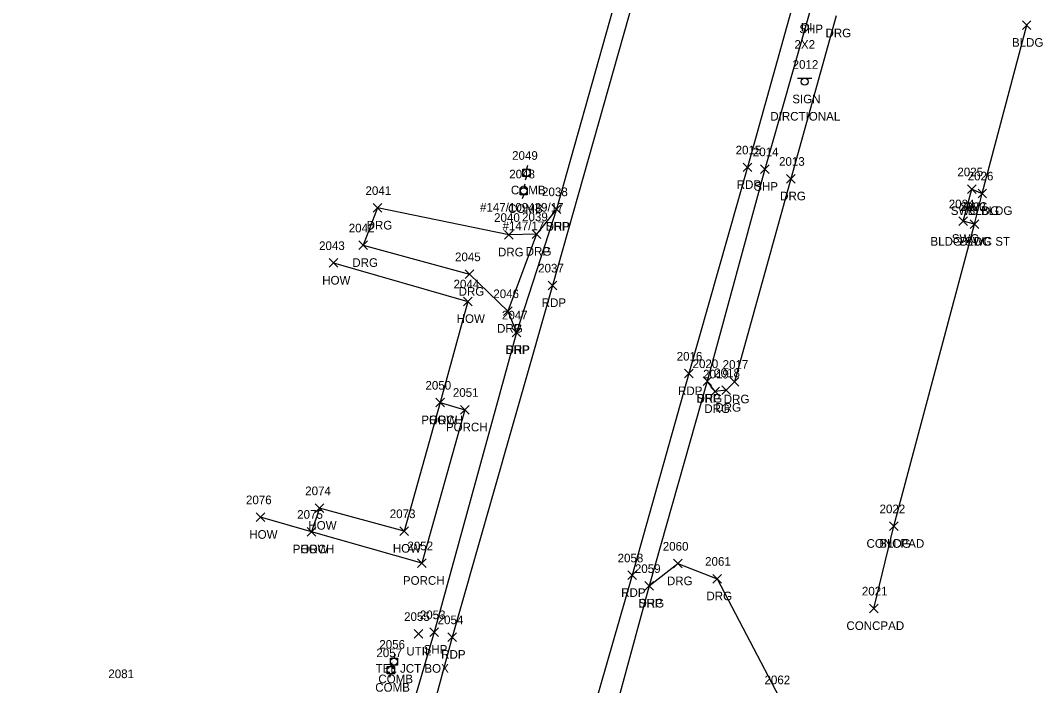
# Model space of a CAD drawing. Extents: x 1443071 to 1445292, y 614024 to 622563.
# Drawn here: x 1444555.8 to 1444792.5, y 622316.6 to 622470.6 of the extents above; entities that cross this region are included whole.
import ezdxf

# ---------------------------------------------------------------- set-up
doc = ezdxf.new("R2010")
doc.units = 0
for name, color, linetype in [('D_A', 7, 'Continuous'), ('D_C', 7, 'Continuous'), ('L_A', 7, 'Continuous'), ('L_I', 7, 'Continuous'), ('L_TIC', 7, 'Continuous'), ('LBC', 7, 'Continuous'), ('LBF', 7, 'Continuous'), ('LS', 7, 'Continuous'), ('P_A', 7, 'Continuous'), ('P_I', 7, 'Continuous'), ('P_TIC', 7, 'Continuous'), ('PET', 7, 'Continuous'), ('PSP', 7, 'Continuous'), ('R_A', 7, 'Continuous'), ('R_I', 7, 'Continuous'), ('R_TIC', 7, 'Continuous'), ('RDG', 7, 'Continuous'), ('RDP', 7, 'Continuous'), ('RSW', 7, 'Continuous'), ('S_A', 7, 'Continuous'), ('S_C', 7, 'Continuous'), ('S_I', 7, 'Continuous'), ('SSGN', 7, 'Continuous'), ('U_A', 7, 'Continuous'), ('U_C', 7, 'Continuous'), ('U_I', 7, 'Continuous'), ('UDEFAULT', 7, 'Continuous'), ('UP', 7, 'Continuous')]:
    doc.layers.add(name, color=color, linetype=linetype)

msp = doc.modelspace()

# ---------------------------------------------------------------- linework, layer by layer
at = {"layer": 'L_TIC'}
for points in [[(1444787.84, 622468.55), (1444789.84, 622470.55)], [(1444789.84, 622468.55), (1444787.84, 622470.55)], [(1444777.57, 622429.6), (1444779.57, 622431.6)], [(1444779.57, 622429.6), (1444777.57, 622431.6)], [(1444775.74, 622422.48), (1444777.74, 622424.48)], [(1444777.74, 622422.48), (1444775.74, 622424.48)], [(1444627.32, 622413.48), (1444629.32, 622415.48)], [(1444629.32, 622413.48), (1444627.32, 622415.48)], [(1444658.46, 622404.59), (1444660.46, 622406.59)], [(1444660.46, 622404.59), (1444658.46, 622406.59)], [(1444652.04, 622381.14), (1444654.04, 622383.14)], [(1444654.04, 622381.14), (1444652.04, 622383.14)], [(1444652.04, 622381.14), (1444654.04, 622383.14)], [(1444654.04, 622381.14), (1444652.04, 622383.14)], [(1444657.73, 622379.48), (1444659.73, 622381.48)], [(1444659.73, 622379.48), (1444657.73, 622381.48)], [(1444624.11, 622356.7), (1444626.11, 622358.7)], [(1444626.11, 622356.7), (1444624.11, 622358.7)], [(1444610.44, 622354.61), (1444612.44, 622356.61)], [(1444612.44, 622354.61), (1444610.44, 622356.61)], [(1444757.11, 622352.52), (1444759.11, 622354.52)], [(1444759.11, 622352.52), (1444757.11, 622354.52)], [(1444757.11, 622352.52), (1444759.11, 622354.52)], [(1444759.11, 622352.52), (1444757.11, 622354.52)], [(1444622.25, 622351.24), (1444624.25, 622353.24)], [(1444624.25, 622351.24), (1444622.25, 622353.24)], [(1444622.25, 622351.24), (1444624.25, 622353.24)], [(1444624.25, 622351.24), (1444622.25, 622353.24)], [(1444643.69, 622351.39), (1444645.69, 622353.39)], [(1444645.69, 622351.39), (1444643.69, 622353.39)], [(1444647.77, 622343.95), (1444649.77, 622345.95)], [(1444649.77, 622343.95), (1444647.77, 622345.95)], [(1444752.45, 622333.48), (1444754.45, 622335.48)], [(1444754.45, 622333.48), (1444752.45, 622335.48)], [(1444752.45, 622333.48), (1444754.45, 622335.48)], [(1444754.45, 622333.48), (1444752.45, 622335.48)]]:
    msp.add_lwpolyline(points, dxfattribs=at)
at = {"layer": 'LBC'}
for points in [[(1444758.11, 622353.52), (1444776.74, 622423.48), (1444778.57, 622430.6), (1444788.84, 622469.55)], [(1444628.32, 622414.48), (1444659.46, 622405.59), (1444653.04, 622382.14), (1444644.69, 622352.39), (1444625.11, 622357.7), (1444623.25, 622352.24), (1444611.44, 622355.61)]]:
    msp.add_lwpolyline(points, dxfattribs=at)
at = {"layer": 'LBF'}
msp.add_lwpolyline([(1444653.04, 622382.14), (1444658.73, 622380.48), (1444648.77, 622344.95), (1444623.25, 622352.24)], dxfattribs=at)
at = {"layer": 'LS'}
msp.add_lwpolyline([(1444753.45, 622334.48), (1444758.11, 622353.52)], dxfattribs=at)
at = {"layer": 'P_TIC'}
for points in [[(1444723.21, 622435.63), (1444725.21, 622437.63)], [(1444725.21, 622435.63), (1444723.21, 622437.63)], [(1444727.21, 622435.2), (1444729.21, 622437.2)], [(1444729.21, 622435.2), (1444727.21, 622437.2)], [(1444678.96, 622425.95), (1444680.96, 622427.95)], [(1444680.96, 622425.95), (1444678.96, 622427.95)], [(1444678.05, 622408.28), (1444680.05, 622410.28)], [(1444680.05, 622408.28), (1444678.05, 622410.28)], [(1444669.67, 622397.4), (1444671.67, 622399.4)], [(1444671.67, 622397.4), (1444669.67, 622399.4)], [(1444709.62, 622387.87), (1444711.62, 622389.87)], [(1444711.62, 622387.87), (1444709.62, 622389.87)], [(1444713.89, 622386.13), (1444715.89, 622388.13)], [(1444715.89, 622386.13), (1444713.89, 622388.13)], [(1444696.45, 622341.15), (1444698.45, 622343.15)], [(1444698.45, 622341.15), (1444696.45, 622343.15)], [(1444700.45, 622338.69), (1444702.45, 622340.69)], [(1444702.45, 622338.69), (1444700.45, 622340.69)], [(1444650.65, 622327.99), (1444652.65, 622329.99)], [(1444652.65, 622327.99), (1444650.65, 622329.99)], [(1444654.77, 622326.83), (1444656.77, 622328.83)], [(1444656.77, 622326.83), (1444654.77, 622328.83)]]:
    msp.add_lwpolyline(points, dxfattribs=at)
at = {"layer": 'PET'}
for points in [[(1444754.44, 622544.13), (1444741.07, 622497.37), (1444724.21, 622436.63), (1444710.62, 622388.87), (1444697.45, 622342.15), (1444675, 622264.13), (1444650.85, 622183.92), (1444630.28, 622116), (1444610.88, 622049.25), (1444594.96, 621996.24), (1444563.37, 621884.27), (1444533.4, 621779.05), (1444495.09, 621640.86), (1444437.04, 621433.18), (1444409.83, 621332.84), (1444393.99, 621275.61), (1444360.23, 621155.32)], [(1444707.59, 622509.11), (1444700.19, 622484.07), (1444679.05, 622409.28), (1444655.77, 622327.83), (1444650.07, 622306.66), (1444636.13, 622255.68), (1444623.55, 622208.8), (1444606.26, 622146.53), (1444595.29, 622106.04), (1444582.56, 622060.23), (1444534.43, 621893.79), (1444481.57, 621704.27), (1444439.29, 621553.82), (1444408.11, 621445.28), (1444395.03, 621397.39), (1444367.96, 621301.44), (1444350.41, 621238.76), (1444319.14, 621126.97)]]:
    msp.add_lwpolyline(points, dxfattribs=at)
at = {"layer": 'PSP'}
for points in [[(1444703.05, 622509.58), (1444696.35, 622485.04), (1444679.96, 622426.95), (1444670.67, 622398.4), (1444651.65, 622328.99), (1444645.77, 622309.01), (1444600.31, 622147.99), (1444589.19, 622108.06), (1444575.49, 622063.15), (1444529.28, 621895.39), (1444476.53, 621706.36), (1444455.46, 621630.82), (1444442.09, 621578.45), (1444424.77, 621519.75), (1444412.09, 621475.26), (1444390.88, 621397.93), (1444363.76, 621301.82), (1444345.99, 621239.2), (1444324.65, 621163.68)], [(1444745.15, 622495.54), (1444738.65, 622472.69), (1444728.21, 622436.2), (1444714.89, 622387.13), (1444701.45, 622339.69), (1444679.77, 622260.17), (1444671.12, 622229.57), (1444657.52, 622182.26), (1444644.19, 622133.53), (1444626.95, 622072.43), (1444608.5, 622007.83), (1444599.1, 621977.5), (1444572.99, 621881.76), (1444551.74, 621805.05), (1444541.41, 621769.53), (1444519.46, 621688.51), (1444505.68, 621638.77), (1444452.32, 621450.13), (1444441.68, 621411.27), (1444418.22, 621330.76), (1444405.98, 621283.95), (1444397.04, 621252.99), (1444383.69, 621203.04)]]:
    msp.add_lwpolyline(points, dxfattribs=at)
at = {"layer": 'R_TIC'}
for points in [[(1444733.26, 622432.99), (1444735.26, 622434.99)], [(1444735.26, 622432.99), (1444733.26, 622434.99)], [(1444775.13, 622430.55), (1444777.13, 622432.55)], [(1444777.13, 622430.55), (1444775.13, 622432.55)], [(1444777.57, 622429.6), (1444779.57, 622431.6)], [(1444779.57, 622429.6), (1444777.57, 622431.6)], [(1444637.51, 622426.23), (1444639.51, 622428.23)], [(1444639.51, 622426.23), (1444637.51, 622428.23)], [(1444678.96, 622425.95), (1444680.96, 622427.95)], [(1444680.96, 622425.95), (1444678.96, 622427.95)], [(1444773.13, 622423.14), (1444775.13, 622425.14)], [(1444775.13, 622423.14), (1444773.13, 622425.14)], [(1444775.74, 622422.48), (1444777.74, 622424.48)], [(1444777.74, 622422.48), (1444775.74, 622424.48)], [(1444667.93, 622420), (1444669.93, 622422)], [(1444669.93, 622420), (1444667.93, 622422)], [(1444674.34, 622420.16), (1444676.34, 622422.16)], [(1444676.34, 622420.16), (1444674.34, 622422.16)], [(1444674.34, 622420.16), (1444676.34, 622422.16)], [(1444676.34, 622420.16), (1444674.34, 622422.16)], [(1444634.18, 622417.57), (1444636.18, 622419.57)], [(1444636.18, 622417.57), (1444634.18, 622419.57)], [(1444658.8, 622410.89), (1444660.8, 622412.89)], [(1444660.8, 622410.89), (1444658.8, 622412.89)], [(1444667.72, 622402.34), (1444669.72, 622404.34)], [(1444669.72, 622402.34), (1444667.72, 622404.34)], [(1444667.72, 622402.34), (1444669.72, 622404.34)], [(1444669.72, 622402.34), (1444667.72, 622404.34)], [(1444669.67, 622397.4), (1444671.67, 622399.4)], [(1444671.67, 622397.4), (1444669.67, 622399.4)], [(1444713.89, 622386.13), (1444715.89, 622388.13)], [(1444715.89, 622386.13), (1444713.89, 622388.13)], [(1444720.2, 622385.97), (1444722.2, 622387.97)], [(1444722.2, 622385.97), (1444720.2, 622387.97)], [(1444715.7, 622383.74), (1444717.7, 622385.74)], [(1444717.7, 622383.74), (1444715.7, 622385.74)], [(1444718.26, 622384.03), (1444720.26, 622386.03)], [(1444720.26, 622384.03), (1444718.26, 622386.03)], [(1444707.05, 622343.86), (1444709.05, 622345.86)], [(1444709.05, 622343.86), (1444707.05, 622345.86)], [(1444700.45, 622338.69), (1444702.45, 622340.69)], [(1444702.45, 622338.69), (1444700.45, 622340.69)], [(1444716.19, 622340.36), (1444718.19, 622342.36)], [(1444718.19, 622340.36), (1444716.19, 622342.36)]]:
    msp.add_lwpolyline(points, dxfattribs=at)
at = {"layer": 'RDG'}
for points in [[(1444744.76, 622471.74), (1444734.26, 622433.99), (1444721.2, 622386.97), (1444719.26, 622385.03), (1444716.7, 622384.74), (1444714.89, 622387.13)], [(1444675.34, 622421.16), (1444668.93, 622421), (1444638.51, 622427.23), (1444635.18, 622418.57), (1444659.8, 622411.89), (1444668.72, 622403.34)], [(1444701.45, 622339.69), (1444708.05, 622344.86), (1444717.19, 622341.36), (1444731.52, 622313.93), (1444723.86, 622290.24), (1444751.94, 622283.05)]]:
    msp.add_lwpolyline(points, dxfattribs=at)
at = {"layer": 'RDP'}
msp.add_lwpolyline([(1444679.96, 622426.95), (1444675.34, 622421.16), (1444668.72, 622403.34), (1444670.67, 622398.4)], dxfattribs=at)
at = {"layer": 'RSW'}
msp.add_lwpolyline([(1444776.74, 622423.48), (1444774.13, 622424.14), (1444776.13, 622431.55), (1444778.57, 622430.6)], dxfattribs=at)
at = {"layer": 'SSGN'}
for p, q in [((1444735.78, 622457.3), (1444739.11, 622457.3)), ((1444737.43, 622456.47), (1444737.43, 622456.47))]:
    msp.add_line(p, q, dxfattribs=at)
msp.add_circle((1444737.43, 622456.47), 0.833, dxfattribs=at)
at = {"layer": 'UDEFAULT'}
for points in [[(1444647.01, 622327.58), (1444649.01, 622329.58)], [(1444649.01, 622327.58), (1444647.01, 622329.58)]]:
    msp.add_lwpolyline(points, dxfattribs=at)
at = {"layer": 'UP'}
for p, q in [((1444672.19, 622434.54), (1444672.19, 622436.2)), ((1444672.19, 622436.2), (1444673.86, 622436.2)), ((1444673.27, 622437.04), (1444673.02, 622436.2)), ((1444673.02, 622435.37), (1444673.02, 622435.37)), ((1444673.86, 622436.2), (1444673.86, 622434.54)), ((1444673.86, 622434.54), (1444672.19, 622434.54)), ((1444672.61, 622432.74), (1444672.36, 622431.91)), ((1444672.77, 622433.7), (1444673.02, 622434.54)), ((1444671.53, 622430.24), (1444671.53, 622431.91)), ((1444671.53, 622431.91), (1444673.19, 622431.91)), ((1444673.19, 622430.24), (1444671.53, 622430.24)), ((1444672.11, 622429.41), (1444672.36, 622430.24)), ((1444672.36, 622431.07), (1444672.36, 622431.07)), ((1444673.19, 622431.91), (1444673.19, 622430.24)), ((1444642.57, 622323.82), (1444642.32, 622322.98)), ((1444641.49, 622321.32), (1444641.49, 622322.98)), ((1444641.49, 622322.98), (1444643.15, 622322.98)), ((1444643.15, 622321.32), (1444641.49, 622321.32)), ((1444641.85, 622321.86), (1444641.6, 622321.03)), ((1444642.07, 622320.48), (1444642.32, 622321.32)), ((1444642.32, 622322.15), (1444642.32, 622322.15)), ((1444643.15, 622322.98), (1444643.15, 622321.32)), ((1444640.77, 622319.36), (1444640.77, 622321.03)), ((1444640.77, 622321.03), (1444642.43, 622321.03)), ((1444642.43, 622319.36), (1444640.77, 622319.36)), ((1444641.35, 622318.53), (1444641.6, 622319.36)), ((1444641.6, 622320.19), (1444641.6, 622320.19)), ((1444642.43, 622321.03), (1444642.43, 622319.36))]:
    msp.add_line(p, q, dxfattribs=at)
for centre in [(1444673.02, 622435.37), (1444672.36, 622431.07), (1444642.32, 622322.15), (1444641.6, 622320.19)]:
    msp.add_circle(centre, 0.833, dxfattribs=at)

# ---------------------------------------------------------------- texts
at = {"layer": 'D_A'}
msp.add_text('DI', height=2, dxfattribs=at).set_placement((1444736.55, 622468.09))
at = {"layer": 'D_C'}
msp.add_text('2X2', height=2, dxfattribs=at).set_placement((1444735.07, 622464.09))
at = {"layer": 'L_A'}
for s, p in [('BLDG', (1444785.43, 622464.55)), ('BLDG', (1444775.17, 622425.6)), ('BLDG', (1444773.33, 622418.48)), ('HOW', (1444625.71, 622409.48)), ('HOW', (1444656.85, 622400.59)), ('PORCH', (1444648.66, 622377.14)), ('HOW', (1444650.43, 622377.14)), ('PORCH', (1444654.35, 622375.48)), ('HOW', (1444622.5, 622352.7)), ('HOW', (1444608.83, 622350.61)), ('CONCPAD', (1444751.75, 622348.52)), ('BLDG', (1444754.7, 622348.52)), ('PORCH', (1444618.87, 622347.24)), ('HOW', (1444620.64, 622347.24)), ('HOW', (1444642.07, 622347.39)), ('PORCH', (1444644.39, 622339.95)), ('CONCPAD', (1444747.1, 622329.48)), ('CONCPAD', (1444747.1, 622329.48))]:
    msp.add_text(s, height=2, dxfattribs=at).set_placement(p)
at = {"layer": 'L_I'}
for s, p in [('2026', (1444775.18, 622433.6)), ('2023', (1444773.4, 622426.48)), ('2043', (1444624.98, 622417.48)), ('2044', (1444656.12, 622408.59)), ('2050', (1444649.62, 622385.14)), ('2050', (1444649.62, 622385.14)), ('2051', (1444655.96, 622383.48)), ('2074', (1444621.77, 622360.7)), ('2076', (1444608.05, 622358.61)), ('2075', (1444619.91, 622355.24)), ('2075', (1444619.91, 622355.24)), ('2073', (1444641.35, 622355.39)), ('2022', (1444754.77, 622356.52)), ('2022', (1444754.77, 622356.52)), ('2052', (1444645.43, 622347.95)), ('2021', (1444750.68, 622337.48)), ('2021', (1444750.68, 622337.48))]:
    msp.add_text(s, height=2, dxfattribs=at).set_placement(p)
at = {"layer": 'P_A'}
for s, p in [('SHP', (1444736.19, 622467.69)), ('RDP', (1444721.7, 622431.63)), ('SHP', (1444725.74, 622431.2)), ('SHP', (1444677.49, 622421.95)), ('RDP', (1444676.54, 622404.28)), ('SHP', (1444668.21, 622393.4)), ('RDP', (1444708.11, 622383.87)), ('SHP', (1444712.43, 622382.13)), ('RDP', (1444694.94, 622337.15)), ('SHP', (1444698.99, 622334.69)), ('SHP', (1444649.19, 622323.99)), ('RDP', (1444653.26, 622322.83))]:
    msp.add_text(s, height=2, dxfattribs=at).set_placement(p)
at = {"layer": 'P_I'}
for s, p in [('2015', (1444721.44, 622439.63)), ('2014', (1444725.43, 622439.2)), ('2038', (1444676.62, 622429.95)), ('2037', (1444675.71, 622412.28)), ('2047', (1444667.33, 622401.4)), ('2016', (1444707.79, 622391.87)), ('2020', (1444711.47, 622390.13)), ('2058', (1444694.11, 622345.15)), ('2059', (1444698.11, 622342.69)), ('2053', (1444648.31, 622331.99)), ('2054', (1444652.43, 622330.83))]:
    msp.add_text(s, height=2, dxfattribs=at).set_placement(p)
at = {"layer": 'R_A'}
for s, p in [('DRG', (1444742.25, 622466.74)), ('DRG', (1444742.25, 622466.74)), ('DRG', (1444731.75, 622428.99)), ('SWC', (1444773.49, 622426.55)), ('SWC BLDG', (1444771.26, 622425.6)), ('DRG', (1444635.99, 622422.23)), ('DRP', (1444677.45, 622421.95)), ('SWC', (1444771.5, 622419.14)), ('BLDG SWC ST', (1444766.56, 622418.48)), ('DRG', (1444666.42, 622416)), ('DRG', (1444672.83, 622416.16)), ('DRP', (1444672.83, 622416.16)), ('DRG', (1444632.67, 622413.57)), ('DRG', (1444657.29, 622406.89)), ('DRG', (1444666.21, 622398.34)), ('DRP', (1444666.21, 622398.34)), ('DRP', (1444668.16, 622393.4)), ('DRG', (1444712.38, 622382.13)), ('DRG', (1444718.69, 622381.97)), ('DRG', (1444714.19, 622379.74)), ('DRG', (1444716.75, 622380.03)), ('DRG', (1444705.53, 622339.86)), ('DRG', (1444714.68, 622336.36)), ('DRG', (1444698.94, 622334.69))]:
    msp.add_text(s, height=2, dxfattribs=at).set_placement(p)
at = {"layer": 'R_I'}
for s, p in [('2013', (1444731.49, 622436.99)), ('2025', (1444772.79, 622434.55)), ('2026', (1444775.18, 622433.6)), ('2041', (1444635.73, 622430.23)), ('2038', (1444676.62, 622429.95)), ('2024', (1444770.8, 622427.14)), ('2023', (1444773.4, 622426.48)), ('2040', (1444665.51, 622424)), ('2039', (1444671.99, 622424.16)), ('2039', (1444671.99, 622424.16)), ('2042', (1444631.85, 622421.57)), ('2045', (1444656.46, 622414.89)), ('2046', (1444665.33, 622406.34)), ('2046', (1444665.33, 622406.34)), ('2047', (1444667.33, 622401.4)), ('2020', (1444711.47, 622390.13)), ('2018', (1444716.49, 622388.03)), ('2017', (1444718.43, 622389.97)), ('2019', (1444713.92, 622387.74)), ('2060', (1444704.57, 622347.86)), ('2061', (1444714.37, 622344.36)), ('2059', (1444698.11, 622342.69)), ('2081', (1444576.18, 622318.33)), ('2062', (1444728.13, 622316.93))]:
    msp.add_text(s, height=2, dxfattribs=at).set_placement(p)
at = {"layer": 'S_A'}
msp.add_text('SIGN', height=2, dxfattribs=at).set_placement((1444734.57, 622451.45))
at = {"layer": 'S_C'}
msp.add_text('DIRCTIONAL', height=2, dxfattribs=at).set_placement((1444729.47, 622447.45))
at = {"layer": 'S_I'}
msp.add_text('2012', height=2, dxfattribs=at).set_placement((1444734.64, 622459.45))
at = {"layer": 'U_A'}
for s, p in [('COMB', (1444669.41, 622430.37)), ('COMB', (1444668.75, 622426.07)), ('UTIL', (1444645.18, 622323.58)), ('COMB', (1444638.71, 622317.15)), ('COMB', (1444637.99, 622315.19))]:
    msp.add_text(s, height=2, dxfattribs=at).set_placement(p)
at = {"layer": 'U_C'}
for s, p in [('#147/109439/17', (1444662.25, 622426.37)), ('#147/17', (1444667.46, 622422.07)), ('TEL JCT BOX', (1444638.08, 622319.58))]:
    msp.add_text(s, height=2, dxfattribs=at).set_placement(p)
at = {"layer": 'U_I'}
for s, p in [('2049', (1444669.68, 622438.37)), ('2048', (1444669.02, 622434.07)), ('2055', (1444644.67, 622331.58)), ('2056', (1444638.93, 622325.15)), ('2057', (1444638.26, 622323.19))]:
    msp.add_text(s, height=2, dxfattribs=at).set_placement(p)

doc.saveas('drawing.dxf')
